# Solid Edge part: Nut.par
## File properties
Author: Vicky Raina
Template: normal.par
Last saved by: Administrator
Revision: 3
Application: Solid Edge
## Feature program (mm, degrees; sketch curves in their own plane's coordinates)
sketch for "unnamed Protrusion 1" plane through (0, 0, 0) normal (0, 0, 1) x-axis (1, 0, 0)
  line (-7.5, 12.9904) -> (-15, 0)
  line (-15, 0) -> (-7.5, -12.9904)
  line (-7.5, -12.9904) -> (7.5, -12.9904)
  line (7.5, -12.9904) -> (15, 0)
  line (15, 0) -> (7.5, 12.9904)
  line (7.5, 12.9904) -> (-7.5, 12.9904)
extrude "unnamed Protrusion 1" add finite 12 symmetric
sketch for "unnamed RevolvedCutout 1" plane through (0, 0, 0) normal (0, -1, 0) x-axis (1, 0, 0)
  arc centre (10, 1) radius 5 from (10, 6) to (15, 1) cw
  line (15, 6) -> (15, 1)
  line (15, 6) -> (10, 6)
revolve "unnamed RevolvedCutout 1" cut full turn 360 deg
mirror "unnamed Mirror 1" of "unnamed RevolvedCutout 1" about plane through (0, 0, 0) normal (0, 0, 1)
revolve "unnamed RevolvedCutout 2" cut full turn 360 deg
sketch for "unnamed Hole 1" plane through (0, 0, 6) normal (0, 0, 1) x-axis (0, 1, 0)
  hole centre (0, 0) bore radius 6
hole "unnamed Hole 1" through
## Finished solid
Body 1: solid body, 11 faces, 22 edges, 12 vertices.
  Faces by surface: plane 8, torus 2, cylinder 1
  Edges by curve: intersection 12, line 6, circle 4
Bounding box of the edges (mm; curved faces can reach further): 30.000 x 25.981 x 12.000, from (-15, -12.9904, -6) to (15, 12.9904, 6).
Cylindrical faces by radius (mm): R6 x1
Toroidal faces (ring radius, tube radius in mm): R10 r5 x2
Planar faces by outward normal: +y 1, +z 1, -y 1, -z 1, oblique 4
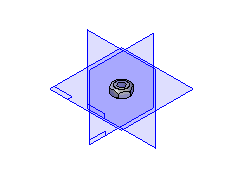
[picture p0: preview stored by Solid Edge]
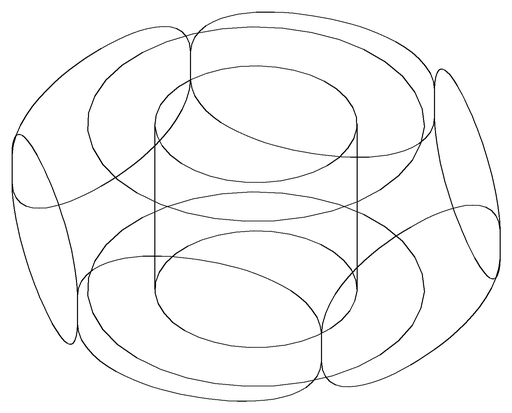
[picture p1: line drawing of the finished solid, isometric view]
